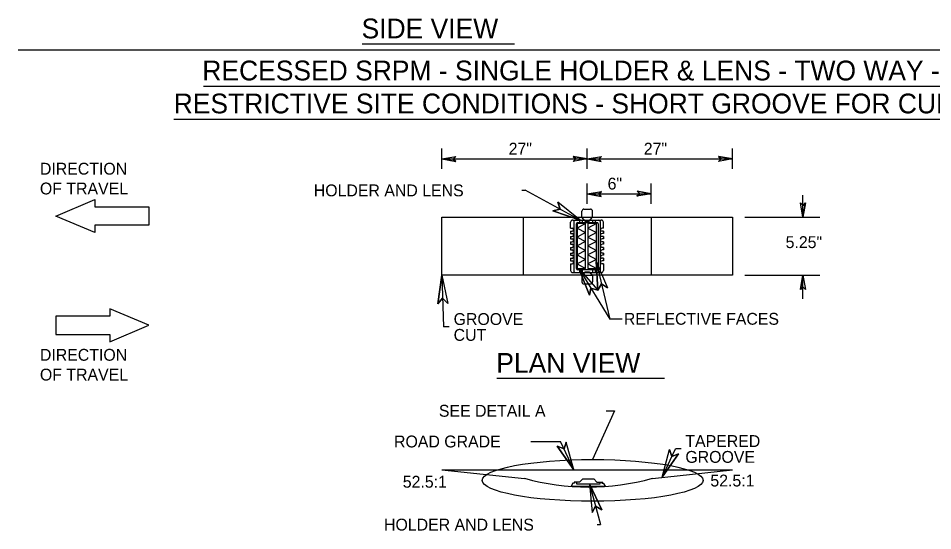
# Model space of a CAD drawing. Extents: x 12.2 to 19.6, y 5.9 to 16.3.
# Drawn here: x 12.247 to 16.872, y 10.779 to 13.369 of the extents above; entities that cross this region are included whole.
import ezdxf

# ---------------------------------------------------------------- set-up
doc = ezdxf.new("R2010")
doc.units = 0
for name, color, linetype in [('BORD-LINE', 7, 'Continuous'), ('C-TRAF-FLOW', 7, 'Continuous'), ('DETL-DIMS', 7, 'Continuous'), ('DETL-LINE', 7, 'Continuous'), ('DETL-NOTE', 7, 'Continuous'), ('DETL-TITL', 7, 'Continuous')]:
    doc.layers.add(name, color=color, linetype=linetype)

msp = doc.modelspace()

# ---------------------------------------------------------------- linework, layer by layer
at = {"layer": 'BORD-LINE'}
msp.add_line((12.2466, 13.2092), (19.6208, 13.2092), dxfattribs=at)
at = {"layer": 'C-TRAF-FLOW'}
for points in [[(12.4365, 12.3696), (12.6338, 12.4532), (12.6338, 12.4165), (12.9062, 12.4165), (12.9062, 12.3227), (12.6338, 12.3227), (12.6338, 12.286)], [(12.9062, 11.8171), (12.7089, 11.9007), (12.7089, 11.864), (12.4365, 11.864), (12.4365, 11.7703), (12.7089, 11.7703), (12.7089, 11.7336)]]:
    msp.add_lwpolyline(points, close=True, dxfattribs=at)
at = {"layer": 'DETL-DIMS'}
for p, q in [((14.3888, 12.6087), (14.3888, 12.7106)), ((15.1243, 12.6087), (15.1243, 12.7106)), ((15.8595, 12.6087), (15.8595, 12.7106)), ((14.3888, 12.6581), (14.4604, 12.6702)), ((14.3888, 12.6581), (14.4602, 12.645)), ((14.3888, 12.6581), (15.1243, 12.6581)), ((14.4468, 12.6577), (14.4604, 12.6702)), ((14.4602, 12.645), (14.4468, 12.6577)), ((15.0663, 12.6585), (15.0527, 12.646)), ((15.1243, 12.6581), (15.0527, 12.646)), ((15.1243, 12.6581), (15.0529, 12.6712)), ((15.0529, 12.6712), (15.0663, 12.6585)), ((15.1243, 12.6581), (15.1959, 12.6702)), ((15.1243, 12.6581), (15.8595, 12.6581)), ((15.1243, 12.6581), (15.1957, 12.645)), ((15.1823, 12.6577), (15.1959, 12.6702)), ((15.1957, 12.645), (15.1823, 12.6577)), ((15.8015, 12.6585), (15.7879, 12.646)), ((15.8595, 12.6581), (15.7879, 12.646)), ((15.8595, 12.6581), (15.7881, 12.6712)), ((15.7881, 12.6712), (15.8015, 12.6585)), ((14.793, 12.5003), (14.8106, 12.5003)), ((15.0888, 12.3491), (14.8106, 12.5003)), ((15.1243, 12.4321), (15.1243, 12.534)), ((15.1243, 12.4816), (15.1959, 12.4937)), ((15.1823, 12.4812), (15.1959, 12.4937)), ((15.4477, 12.4816), (15.3763, 12.4947)), ((15.3763, 12.4947), (15.3897, 12.482)), ((15.4477, 12.4321), (15.4477, 12.534)), ((15.1243, 12.4816), (15.1957, 12.4685)), ((15.1243, 12.4816), (15.4477, 12.4816)), ((15.1957, 12.4685), (15.1823, 12.4812)), ((15.3897, 12.482), (15.3761, 12.4695)), ((15.4477, 12.4816), (15.3761, 12.4695)), ((16.2156, 12.3642), (16.2156, 12.4759)), ((14.9511, 12.3953), (14.9868, 12.4046)), ((15.0888, 12.3491), (14.9751, 12.4396)), ((14.9868, 12.4046), (14.9751, 12.4396)), ((16.2156, 12.3642), (16.2035, 12.4358)), ((16.216, 12.4222), (16.2035, 12.4358)), ((16.2156, 12.3642), (16.2287, 12.4356)), ((16.2287, 12.4356), (16.216, 12.4222)), ((15.0888, 12.3491), (14.9511, 12.3953)), ((15.921, 12.3642), (16.3001, 12.3642)), ((15.17, 12.1403), (15.1782, 11.9954)), ((15.17, 12.1403), (15.2272, 12.0069)), ((15.17, 12.1403), (15.2388, 11.8476)), ((15.0823, 12.1044), (15.1352, 11.9692)), ((15.0823, 12.1044), (15.1782, 11.9954)), ((15.0823, 12.1044), (15.2388, 11.8476)), ((14.3888, 12.0701), (14.3688, 11.9263)), ((14.3888, 12.0701), (14.3982, 11.8088)), ((14.3888, 12.0701), (14.4191, 11.9281)), ((15.1782, 11.9954), (15.1965, 12.0274)), ((15.1965, 12.0274), (15.2272, 12.0069)), ((15.921, 12.07), (16.3001, 12.07)), ((16.2156, 12.07), (16.2025, 11.9986)), ((16.2156, 12.07), (16.2277, 11.9984)), ((16.2156, 11.9513), (16.2156, 12.07)), ((15.1352, 11.9692), (15.1427, 12.0053)), ((15.1427, 12.0053), (15.1782, 11.9954)), ((16.2025, 11.9986), (16.2152, 12.012)), ((16.2152, 12.012), (16.2277, 11.9984)), ((14.3688, 11.9263), (14.3929, 11.9541)), ((14.3929, 11.9541), (14.4191, 11.9281)), ((15.3006, 11.8476), (15.2388, 11.8476)), ((14.4265, 11.8088), (14.3982, 11.8088)), ((14.8386, 11.2299), (14.9894, 11.2299)), ((15.0559, 11.0866), (14.9729, 11.2057)), ((14.9729, 11.2057), (15.0071, 11.1919)), ((15.0559, 11.0866), (14.9894, 11.2299)), ((15.0071, 11.1919), (15.0185, 11.227)), ((15.0559, 11.0866), (15.0185, 11.227)), ((15.5038, 11.0488), (15.5703, 11.192)), ((15.5038, 11.0488), (15.5412, 11.1891)), ((15.5038, 11.0488), (15.5868, 11.1679)), ((15.5527, 11.1541), (15.5412, 11.1891)), ((15.5868, 11.1679), (15.5527, 11.1541)), ((15.5987, 11.192), (15.5703, 11.192)), ((15.1355, 11.015), (15.1923, 10.8108)), ((15.1355, 11.015), (15.1981, 10.884)), ((15.1355, 11.015), (15.1496, 10.8704)), ((15.1666, 10.9032), (15.1496, 10.8704)), ((15.1981, 10.884), (15.1666, 10.9032)), ((15.1748, 10.8108), (15.1923, 10.8108))]:
    msp.add_line(p, q, dxfattribs=at)
for points in [[(14.4602, 12.645), (14.3888, 12.6581), (14.4604, 12.6702), (14.4468, 12.6577)], [(15.0529, 12.6712), (15.1243, 12.6581), (15.0527, 12.646), (15.0663, 12.6585)], [(15.1957, 12.645), (15.1243, 12.6581), (15.1959, 12.6702), (15.1823, 12.6577)], [(15.7881, 12.6712), (15.8595, 12.6581), (15.7879, 12.646), (15.8015, 12.6585)], [(15.1957, 12.4685), (15.1243, 12.4816), (15.1959, 12.4937), (15.1823, 12.4812)], [(15.3763, 12.4947), (15.4477, 12.4816), (15.3761, 12.4695), (15.3897, 12.482)], [(14.9511, 12.3953), (15.0888, 12.3491), (14.9751, 12.4396), (14.9868, 12.4046)], [(16.2287, 12.4356), (16.2156, 12.3642), (16.2035, 12.4358), (16.216, 12.4222)], [(15.1782, 11.9954), (15.17, 12.1403), (15.2272, 12.0069), (15.1965, 12.0274)], [(15.1352, 11.9692), (15.0823, 12.1044), (15.1782, 11.9954), (15.1427, 12.0053)], [(14.3688, 11.9263), (14.3888, 12.0701), (14.4191, 11.9281), (14.3929, 11.9541)], [(16.2025, 11.9986), (16.2156, 12.07), (16.2277, 11.9984), (16.2152, 12.012)], [(14.9729, 11.2057), (15.0559, 11.0866), (15.0185, 11.227), (15.0071, 11.1919)], [(15.5868, 11.1679), (15.5038, 11.0488), (15.5412, 11.1891), (15.5527, 11.1541)], [(15.1981, 10.884), (15.1355, 11.015), (15.1496, 10.8704), (15.1666, 10.9032)]]:
    msp.add_lwpolyline(points, close=True, dxfattribs=at)
msp.add_lwpolyline([(15.2209, 11.3855), (15.2629, 11.3855), (15.1517, 11.1387)], dxfattribs=at)
at = {"layer": 'DETL-LINE'}
for p, q in [((15.1078, 12.4045), (15.1408, 12.4045)), ((14.8009, 12.3642), (14.8009, 12.0701)), ((15.0968, 12.3642), (15.1515, 12.3642)), ((15.0972, 12.3638), (15.0972, 12.3939)), ((15.1145, 12.3436), (15.0972, 12.3638)), ((15.1341, 12.3436), (15.1515, 12.3638)), ((15.1515, 12.3638), (15.1515, 12.3939)), ((15.0404, 12.3086), (15.0404, 12.3385)), ((15.0404, 12.3086), (15.0475, 12.3086)), ((15.051, 12.3491), (15.1957, 12.3491)), ((15.0566, 12.3428), (15.0566, 12.0902)), ((15.0734, 12.3318), (15.0734, 12.1046)), ((15.1161, 12.3318), (15.0734, 12.3318)), ((15.1161, 12.3318), (15.0734, 12.3091)), ((15.0734, 12.3091), (15.1161, 12.2863)), ((15.0846, 12.3491), (15.0846, 12.3366)), ((15.0984, 12.3491), (15.0984, 12.3366)), ((15.1145, 12.3436), (15.1341, 12.3436)), ((15.1161, 12.1046), (15.1161, 12.3318)), ((15.1282, 12.3318), (15.1282, 12.1046)), ((15.171, 12.3318), (15.1282, 12.3318)), ((15.171, 12.3318), (15.1282, 12.3091)), ((15.1282, 12.3091), (15.171, 12.2863)), ((15.1503, 12.3491), (15.1503, 12.3366)), ((15.1642, 12.3491), (15.1642, 12.3366)), ((15.171, 12.1046), (15.171, 12.3318)), ((15.1901, 12.3428), (15.1901, 12.0902)), ((15.2063, 12.3086), (15.1992, 12.3086)), ((15.2063, 12.3086), (15.2063, 12.3385)), ((15.0404, 12.2929), (15.0404, 12.2816)), ((15.0404, 12.2929), (15.0475, 12.2929)), ((15.0404, 12.2816), (15.0475, 12.2816)), ((15.0404, 12.2659), (15.0404, 12.2541)), ((15.0404, 12.2659), (15.0475, 12.2659)), ((15.1161, 12.2863), (15.0734, 12.2636)), ((15.0734, 12.2636), (15.1161, 12.2409)), ((15.171, 12.2863), (15.1282, 12.2636)), ((15.1282, 12.2636), (15.171, 12.2409)), ((15.2063, 12.2929), (15.1992, 12.2929)), ((15.2063, 12.2816), (15.1992, 12.2816)), ((15.2063, 12.2659), (15.1992, 12.2659)), ((15.2063, 12.2929), (15.2063, 12.2816)), ((15.2063, 12.2659), (15.2063, 12.2541)), ((15.0404, 12.2541), (15.0475, 12.2541)), ((15.0404, 12.2384), (15.0404, 12.2269)), ((15.0404, 12.2384), (15.0475, 12.2384)), ((15.0404, 12.2269), (15.0475, 12.2269)), ((15.0404, 12.2112), (15.0404, 12.1981)), ((15.0404, 12.2112), (15.0475, 12.2112)), ((15.1161, 12.2409), (15.0734, 12.2182)), ((15.0734, 12.2182), (15.1161, 12.1955)), ((15.171, 12.2409), (15.1282, 12.2182)), ((15.1282, 12.2182), (15.171, 12.1955)), ((15.2063, 12.2541), (15.1992, 12.2541)), ((15.2063, 12.2384), (15.1992, 12.2384)), ((15.2063, 12.2269), (15.1992, 12.2269)), ((15.2063, 12.2112), (15.1992, 12.2112)), ((15.2063, 12.2384), (15.2063, 12.2269)), ((15.2063, 12.2112), (15.2063, 12.1981)), ((15.0404, 12.1981), (15.0475, 12.1981)), ((15.0404, 12.1824), (15.0404, 12.1715)), ((15.0404, 12.1824), (15.0475, 12.1824)), ((15.0404, 12.1715), (15.0475, 12.1715)), ((15.1161, 12.1955), (15.0734, 12.1727)), ((15.0734, 12.1727), (15.1161, 12.15)), ((15.171, 12.1955), (15.1282, 12.1727)), ((15.1282, 12.1727), (15.171, 12.15)), ((15.2063, 12.1981), (15.1992, 12.1981)), ((15.2063, 12.1824), (15.1992, 12.1824)), ((15.2063, 12.1715), (15.1992, 12.1715)), ((15.2063, 12.1824), (15.2063, 12.1715)), ((15.0404, 12.1558), (15.0404, 12.1438)), ((15.0404, 12.1558), (15.0475, 12.1558)), ((15.0404, 12.1438), (15.0475, 12.1438)), ((15.0404, 12.1281), (15.0475, 12.1281)), ((15.0404, 12.1277), (15.0404, 12.0945)), ((15.1161, 12.15), (15.0734, 12.1273)), ((15.0734, 12.1273), (15.1161, 12.1046)), ((15.171, 12.15), (15.1282, 12.1273)), ((15.1282, 12.1273), (15.171, 12.1046)), ((15.2063, 12.1558), (15.1992, 12.1558)), ((15.2063, 12.1438), (15.1992, 12.1438)), ((15.2063, 12.1281), (15.1992, 12.1281)), ((15.2063, 12.1558), (15.2063, 12.1438)), ((15.2063, 12.1277), (15.2063, 12.0945)), ((15.051, 12.0838), (15.1957, 12.0838)), ((15.0734, 12.1046), (15.1161, 12.1046)), ((15.0846, 12.098), (15.0846, 12.0838)), ((15.1145, 12.087), (15.0972, 12.0668)), ((15.0984, 12.098), (15.0984, 12.0838)), ((15.1145, 12.087), (15.1341, 12.087)), ((15.1282, 12.1046), (15.171, 12.1046)), ((15.1341, 12.087), (15.1515, 12.0668)), ((15.1503, 12.098), (15.1503, 12.0838)), ((15.1642, 12.098), (15.1642, 12.0838)), ((15.0972, 12.0668), (15.0972, 12.0367)), ((15.1, 12.0701), (15.1487, 12.0701)), ((15.1078, 12.0261), (15.1408, 12.0261)), ((15.1515, 12.0668), (15.1515, 12.0367)), ((14.3888, 11.0866), (14.8071, 11.0435)), ((14.3888, 11.0866), (15.8595, 11.0866)), ((15.454, 11.0435), (15.8595, 11.0866)), ((15.0516, 11.0197), (15.0438, 11.0046)), ((15.0593, 11.0197), (15.0516, 11.0197)), ((15.0577, 11.0259), (15.0875, 11.0259)), ((15.0593, 11.0259), (15.0593, 11.0197)), ((15.0705, 11.0259), (15.0705, 11.0161)), ((15.0705, 11.0161), (15.19, 11.0161)), ((15.0875, 11.0259), (15.1025, 11.0414)), ((15.1025, 11.0414), (15.1581, 11.0414)), ((15.1581, 11.0414), (15.1729, 11.0248)), ((15.1729, 11.0248), (15.2032, 11.0248)), ((15.19, 11.0161), (15.19, 11.0248)), ((15.1996, 11.0178), (15.1996, 11.0248)), ((15.2084, 11.0178), (15.1996, 11.0178)), ((15.2167, 11.0046), (15.2084, 11.0178)), ((15.0438, 11.0046), (15.2167, 11.0046))]:
    msp.add_line(p, q, dxfattribs=at)
for points in [[(15.1, 12.0701), (14.3888, 12.0701), (14.3888, 12.3642), (15.0972, 12.3642)], [(15.1515, 12.3642), (15.8595, 12.3642), (15.8595, 12.0701), (15.1487, 12.0701)], [(15.4477, 12.3642), (15.4477, 12.0701)], [(15.0693, 12.1044), (15.0693, 12.3302)], [(15.0757, 12.3366), (15.1731, 12.3366)], [(15.1794, 12.3302), (15.1794, 12.1044)], [(15.1731, 12.098), (15.0757, 12.098)]]:
    msp.add_lwpolyline(points, dxfattribs=at)
for centre, radius, start, end in [((15.1078, 12.3939), 0.0106, 90, 180), ((15.1408, 12.3939), 0.0106, 0, 90), ((15.051, 12.3385), 0.0106, 90, 180), ((15.0475, 12.3008), 0.00785, 270, 90), ((15.063, 12.3428), 0.00638, 90, 180), ((15.0757, 12.3302), 0.00638, 90, 180), ((15.1731, 12.3302), 0.00638, 0, 90), ((15.1837, 12.3428), 0.00638, 0, 90), ((15.1992, 12.3008), 0.00785, 90, 270), ((15.1957, 12.3385), 0.0106, 0, 90), ((15.0475, 12.2737), 0.00785, 270, 90), ((15.1992, 12.2737), 0.00785, 90, 270), ((15.0475, 12.2463), 0.00785, 270, 90), ((15.0475, 12.219), 0.00785, 270, 90), ((15.1992, 12.2463), 0.00785, 90, 270), ((15.1992, 12.219), 0.00785, 90, 270), ((15.0475, 12.1902), 0.00785, 270, 90), ((15.0475, 12.1636), 0.00785, 270, 90), ((15.1992, 12.1902), 0.00785, 90, 270), ((15.1992, 12.1636), 0.00785, 90, 270), ((15.0475, 12.1359), 0.00785, 270, 90), ((15.1992, 12.1359), 0.00785, 90, 270), ((15.051, 12.0945), 0.0106, 180, 270), ((15.063, 12.0902), 0.00638, 180, 270), ((15.0757, 12.1044), 0.00638, 180, 270), ((15.1731, 12.1044), 0.00638, 270, 0), ((15.1837, 12.0902), 0.00638, 270, 0), ((15.1957, 12.0945), 0.0106, 270, 0), ((15.1078, 12.0367), 0.0106, 180, 270), ((15.1408, 12.0367), 0.0106, 270, 0), ((15.1305, 12.2061), 1.2067, 254.4536, 285.5464)]:
    msp.add_arc(centre, radius, start, end, dxfattribs=at)
msp.add_ellipse((15.1517, 11.0332), major_axis=(0.5585, 0), ratio=0.188991, dxfattribs=at)
at = {"layer": 'DETL-TITL'}
for p, q in [((13.9863, 13.241), (14.7558, 13.241)), ((13.1831, 13.0257), (18.6888, 13.0257)), ((13.0328, 12.859), (18.836, 12.859)), ((14.6676, 11.55), (15.5149, 11.55))]:
    msp.add_line(p, q, dxfattribs=at)

# ---------------------------------------------------------------- texts
at = {"layer": 'DETL-NOTE'}
for s, p in [('27"', (14.7269, 12.6801)), ('27"', (15.4105, 12.6801)), ('DIRECTION ', (12.356, 12.5788)), ('OF TRAVEL', (12.356, 12.4788)), ('6"', (15.2274, 12.5035)), ('HOLDER AND LENS', (13.7413, 12.4692)), ('5.25"', (16.1279, 12.2076)), ('GROOVE', (14.4486, 11.8187)), ('REFLECTIVE FACES', (15.3097, 11.82)), ('CUT', (14.4486, 11.7387)), ('DIRECTION ', (12.356, 11.6379)), ('OF TRAVEL', (12.356, 11.5379)), ('SEE DETAIL A', (14.3741, 11.355)), ('ROAD GRADE', (14.1472, 11.1997)), ('TAPERED', (15.6207, 11.2019)), ('GROOVE', (15.6207, 11.1219)), ('52.5:1', (14.1915, 10.9963)), ('52.5:1', (15.7472, 11.0023)), ('HOLDER AND LENS', (14.0966, 10.7796))]:
    msp.add_text(s, height=0.06, dxfattribs=at).set_placement(p)
at = {"layer": 'DETL-TITL'}
for s, p in [('SIDE VIEW', (13.9829, 13.2678)), ('RECESSED SRPM - SINGLE HOLDER & LENS - TWO WAY - CENTERLINE', (13.1775, 13.0553)), ('RESTRICTIVE SITE CONDITIONS - SHORT GROOVE FOR CURVED ALIGNMENT', (13.0327, 12.8886)), ('PLAN VIEW', (14.6644, 11.5769))]:
    msp.add_text(s, height=0.1, dxfattribs=at).set_placement(p)

doc.saveas('drawing.dxf')
